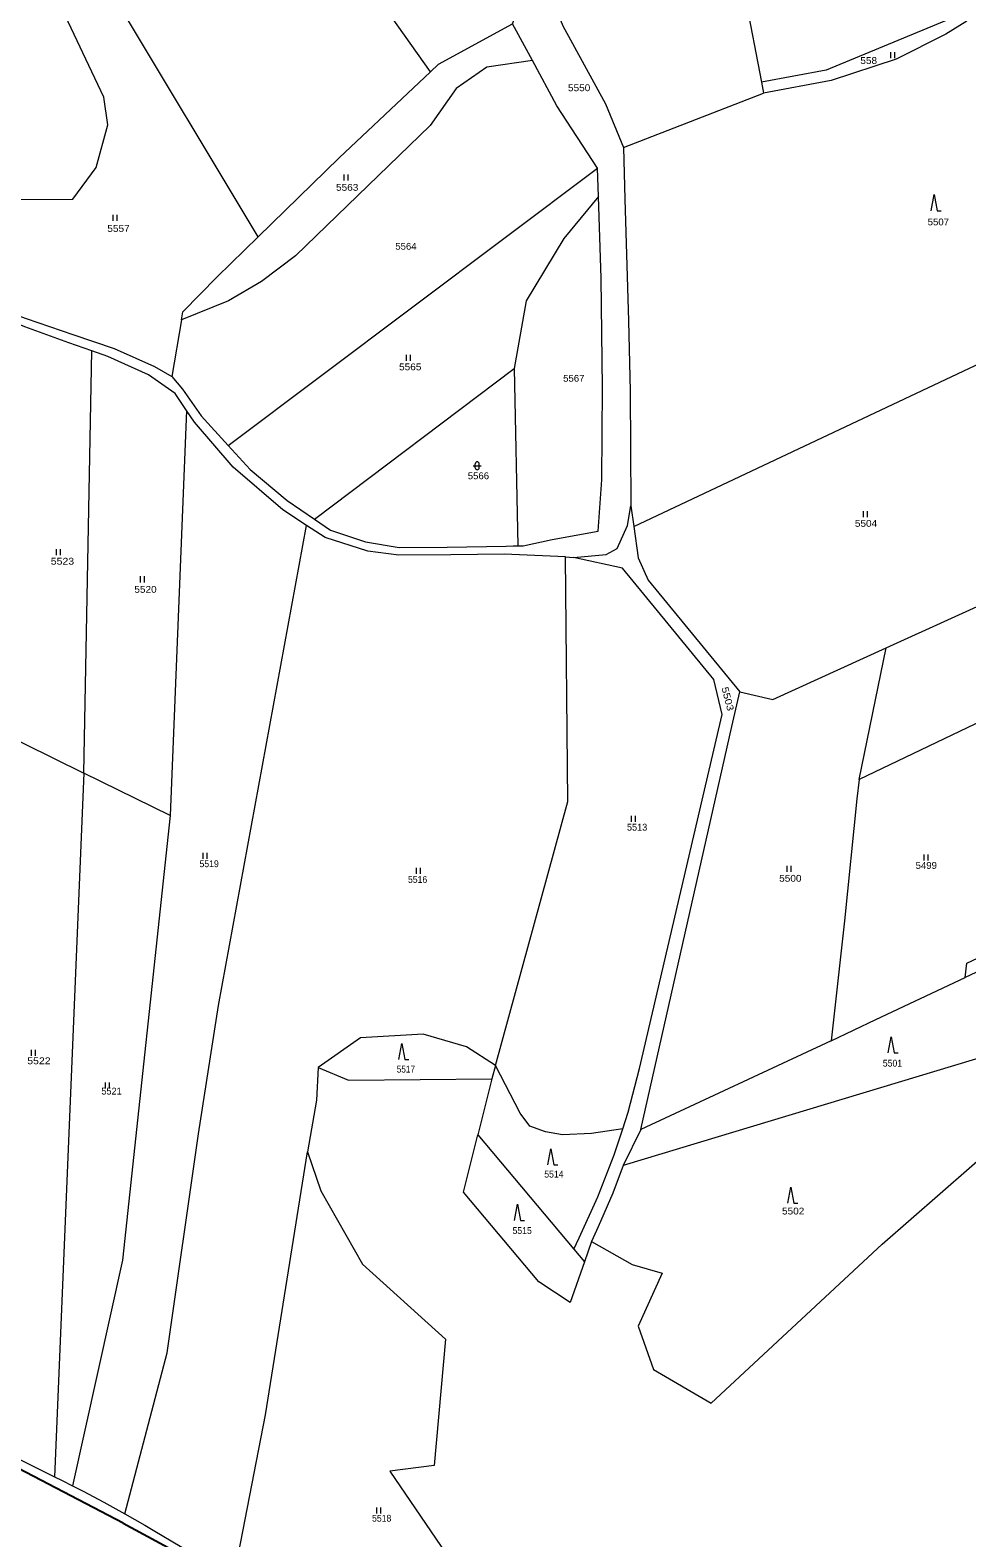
# Model space of a CAD drawing. Extents: x -590528 to -586543, y -1119609 to -1116685.
# Drawn here: x -589555 to -589321.5, y -1118965.6 to -1118589.8 of the extents above; entities that cross this region are included whole.
import ezdxf
from ezdxf.enums import TextEntityAlignment as Align

# ---------------------------------------------------------------- set-up
doc = ezdxf.new("R2010")
doc.units = 0
doc.header["$LTSCALE"] = 0.68
for name, color, linetype, lineweight in [('1', 7, 'Continuous', 13), ('3', 7, 'Continuous', 13), ('4', 7, 'Continuous', 25), ('6', 7, 'Continuous', 13)]:
    doc.layers.add(name, color=color, linetype=linetype, lineweight=lineweight)

msp = doc.modelspace()

# ---------------------------------------------------------------- linework, layer by layer
at = {"layer": '1'}
for p, q in [((-589377.91, -1118575.64), (-589372.7, -1118602.82)), ((-589498.15, -1118641.31), (-589534.97, -1118579.92)), ((-589324.31, -1118586.45), (-589356.56, -1118599.76)), ((-589429.8, -1118597.4), (-589434.75, -1118588.2)), ((-589356.56, -1118599.76), (-589372.7, -1118602.82)), ((-589372.7, -1118602.82), (-589372.18, -1118605.52)), ((-589505.53, -1118657.26), (-589517.23, -1118661.98)), ((-589484.08, -1118711.72), (-589434.36, -1118674.15)), ((-589515.97, -1118684.58), (-589520.04, -1118785.53)), ((-589405.24, -1118708.4), (-589404.53, -1118713.52)), ((-589508.04, -1118832.9), (-589486.09, -1118713.25)), ((-589420.96, -1118782.08), (-589421.59, -1118721.13)), ((-589382.53, -1118760.42), (-589384.56, -1118751.68)), ((-589380.13, -1118763.35), (-589378.14, -1118754.78)), ((-589402.77, -1118863.84), (-589380.13, -1118763.35)), ((-589541.55, -1118775), (-589548.89, -1118950.37)), ((-589520.04, -1118785.53), (-589541.55, -1118775)), ((-589348.37, -1118776.57), (-589348.94, -1118781.39)), ((-589439, -1118847.87), (-589420.96, -1118782.08)), ((-589520.04, -1118785.53), (-589531.99, -1118896.42)), ((-589513.04, -1118864.93), (-589508.04, -1118832.9)), ((-589355.38, -1118841.69), (-589402.77, -1118863.84)), ((-589446.98, -1118879.42), (-589443.41, -1118865.17)), ((-589443.41, -1118865.17), (-589419.5, -1118893.66)), ((-589402.77, -1118863.84), (-589407.16, -1118872.82)), ((-589407.16, -1118872.82), (-589409.8, -1118879.72)), ((-589419.5, -1118893.66), (-589416.85, -1118896.83)), ((-589385.25, -1118932.01), (-589342.68, -1118892.44)), ((-589557.38, -1118946.17), (-589548.89, -1118950.37)), ((-589523.89, -1118963.95), (-589504.19, -1118975.57))]:
    msp.add_line(p, q, dxfattribs=at)
for points in [[(-589455.19, -1118600.2), (-589477.85, -1118568.1), (-589490.34, -1118532.23), (-589503.08, -1118514.55)], [(-589536.6, -1118606.53), (-589558.87, -1118559.4), (-589570.68, -1118533.18), (-589560.7, -1118524.73), (-589551.05, -1118519.91), (-589569.71, -1118522), (-589581.21, -1118530.01)], [(-589455.19, -1118600.2), (-589453.19, -1118598.32), (-589434.75, -1118588.2), (-589427.97, -1118570.44), (-589423.37, -1118562.13), (-589416.01, -1118553.98), (-589405.46, -1118542.79), (-589395.65, -1118531.99), (-589381.98, -1118517.45)], [(-589383.31, -1118553.86), (-589389.82, -1118531.63), (-589409.4, -1118552.26), (-589421.86, -1118565.56), (-589425.96, -1118574.55), (-589424.61, -1118582.96), (-589422.21, -1118588.7), (-589411.59, -1118608.16)], [(-589321.57, -1118587.58), (-589326.81, -1118590.78), (-589339.12, -1118597.03), (-589355.39, -1118602.34), (-589372.18, -1118605.52)], [(-589423.74, -1118608.66), (-589429.8, -1118597.4), (-589441.19, -1118599), (-589448.81, -1118604.39)], [(-589508.4, -1118651.29), (-589498.15, -1118641.31), (-589477.95, -1118621.64), (-589455.19, -1118600.2)], [(-589448.81, -1118604.39), (-589455.26, -1118613.61), (-589488.87, -1118646.06), (-589497.28, -1118652.48), (-589505.53, -1118657.26)], [(-589411.59, -1118608.16), (-589407.1, -1118619.03), (-589372.18, -1118605.52)], [(-589568.44, -1118632.03), (-589544.29, -1118631.95), (-589538.54, -1118624.06), (-589535.64, -1118613.45), (-589536.6, -1118606.53)], [(-589505.61, -1118693.38), (-589413.55, -1118624.2), (-589423.74, -1118608.66)], [(-589407.1, -1118619.03), (-589406.77, -1118631.91), (-589405.9, -1118662.26), (-589405.43, -1118679.83), (-589405.24, -1118708.4)], [(-589412.5, -1118701.91), (-589412.33, -1118678.99), (-589412.71, -1118651.67), (-589413.33, -1118631.27), (-589413.55, -1118624.2)], [(-589413.33, -1118631.27), (-589421.95, -1118641.76), (-589431.34, -1118657.32), (-589434.36, -1118674.15)], [(-589517.23, -1118661.98), (-589516.9, -1118660.06), (-589508.4, -1118651.29)], [(-589404.53, -1118713.52), (-589319.45, -1118673.42), (-589271.29, -1118650.72), (-589254.18, -1118703.14)], [(-589565.14, -1118658.15), (-589557.12, -1118661.25), (-589555.95, -1118661.7), (-589544.29, -1118665.7), (-589534.06, -1118669.18), (-589524.02, -1118673.65), (-589519.64, -1118676.13)], [(-589539.62, -1118669.73), (-589545.34, -1118667.74), (-589556.31, -1118663.73), (-589558.69, -1118662.75)], [(-589517.23, -1118661.98), (-589519.64, -1118676.13), (-589516.98, -1118679.31), (-589512.38, -1118685.93), (-589505.61, -1118693.38)], [(-589567.43, -1118762.33), (-589564.04, -1118763.99), (-589541.55, -1118775), (-589539.62, -1118669.73)], [(-589515.97, -1118684.58), (-589518.79, -1118680.35), (-589525.5, -1118675.71), (-589535.63, -1118671.12), (-589539.62, -1118669.73)], [(-589434.36, -1118674.15), (-589433.44, -1118718.37), (-589432.1, -1118718.35), (-589424.9, -1118716.79), (-589413.39, -1118714.68), (-589412.5, -1118701.91)], [(-589504.39, -1118698.7), (-589514, -1118687.54), (-589515.97, -1118684.58)], [(-589505.61, -1118693.38), (-589500.18, -1118699.36), (-589490.93, -1118707.06), (-589484.08, -1118711.72), (-589480.12, -1118714.42), (-589471.38, -1118717.37), (-589462.99, -1118718.77), (-589451.03, -1118718.72)], [(-589486.09, -1118713.25), (-589491.99, -1118709.38), (-589504.39, -1118698.7)], [(-589256.7, -1118732.69), (-589313.85, -1118760.05), (-589348.37, -1118776.57), (-589341.68, -1118743.8), (-589294.6, -1118722.4), (-589254.18, -1118703.14)], [(-589421.59, -1118721.13), (-589419.55, -1118721.23), (-589411.44, -1118720.54), (-589408.69, -1118719.02), (-589406.14, -1118713.27), (-589405.24, -1118708.4)], [(-589450.15, -1118720.61), (-589463.09, -1118720.67), (-589470.79, -1118719.7), (-589481.48, -1118716.27), (-589486.09, -1118713.25)], [(-589404.53, -1118713.52), (-589403.45, -1118721.3), (-589400.98, -1118726.9), (-589378.14, -1118754.78)], [(-589451.03, -1118718.72), (-589436.38, -1118718.41), (-589434.64, -1118718.39), (-589433.44, -1118718.37)], [(-589421.59, -1118721.13), (-589436.83, -1118720.39), (-589450.15, -1118720.61)], [(-589384.56, -1118751.68), (-589407.33, -1118723.89), (-589419.55, -1118721.23)], [(-589378.14, -1118754.78), (-589369.9, -1118756.62), (-589341.68, -1118743.8)], [(-589407.31, -1118863.69), (-589405.95, -1118859.51), (-589403.1, -1118848.66), (-589382.53, -1118760.42)], [(-589348.94, -1118781.39), (-589352.05, -1118811.84), (-589355.38, -1118841.69), (-589344.19, -1118836.41), (-589321.93, -1118825.91)], [(-589308.68, -1118819.69), (-589321.93, -1118825.91), (-589321.52, -1118822.4), (-589295.55, -1118810.14), (-589278.56, -1118809.42), (-589264.1, -1118802.62)], [(-589439, -1118847.87), (-589446.2, -1118843.22), (-589457.04, -1118840.09), (-589472.63, -1118841.02), (-589483.18, -1118848.39)], [(-589342.68, -1118892.44), (-589306.51, -1118860.81), (-589304.51, -1118856.92), (-589306.14, -1118842.33), (-589407.16, -1118872.82)], [(-589483.18, -1118848.39), (-589483.58, -1118856.49), (-589485.85, -1118869.38), (-589482.5, -1118879.11)], [(-589483.18, -1118848.39), (-589475.67, -1118851.55), (-589439.9, -1118851.16)], [(-589413.48, -1118880.64), (-589409.42, -1118870.18), (-589407.31, -1118863.69), (-589415.12, -1118864.81), (-589422.32, -1118865.14), (-589426.54, -1118864.38), (-589430.46, -1118862.98), (-589432.85, -1118859.74), (-589439, -1118847.87), (-589439.9, -1118851.16), (-589443.41, -1118865.17)], [(-589531.99, -1118896.42), (-589544.4, -1118952.65), (-589541.79, -1118953.99), (-589536.62, -1118956.74), (-589531.38, -1118959.63), (-589520.84, -1118919.51), (-589513.04, -1118864.93)], [(-589504.19, -1118975.57), (-589496.34, -1118934.92), (-589485.85, -1118869.38)], [(-589482.5, -1118879.11), (-589472.13, -1118897.43), (-589451.47, -1118916.1), (-589454.26, -1118947.58), (-589465.34, -1118949.01), (-589450.02, -1118971.42)], [(-589415.1, -1118891.78), (-589416.85, -1118896.83), (-589420.37, -1118906.99), (-589428.21, -1118901.79), (-589446.98, -1118879.42)], [(-589419.5, -1118893.66), (-589418.13, -1118890.86), (-589413.48, -1118880.64)], [(-589409.8, -1118879.72), (-589413.43, -1118888.08), (-589415.1, -1118891.78), (-589404.91, -1118897.46), (-589397.44, -1118899.64), (-589403.43, -1118912.82), (-589399.63, -1118923.62), (-589385.25, -1118932.01)], [(-589548.89, -1118950.37), (-589547, -1118951.31), (-589544.4, -1118952.65)], [(-589531.38, -1118959.63), (-589526.41, -1118962.47), (-589523.89, -1118963.95)]]:
    msp.add_lwpolyline(points, dxfattribs=at)
at = {"layer": '4'}
for q in [(-589564.78, -1118944.76), (-589515.51, -1118970.74)]:
    msp.add_line((-589531.82, -1118961.95), q, dxfattribs=at)
at = {"layer": '6'}
for p, q in [((-589340.52, -1118596.78), (-589340.52, -1118595.28)), ((-589339.52, -1118596.78), (-589339.52, -1118595.28)), ((-589476.75, -1118627.32), (-589476.75, -1118625.82)), ((-589475.75, -1118627.32), (-589475.75, -1118625.82)), ((-589534.32, -1118637.36), (-589534.32, -1118635.86)), ((-589533.32, -1118637.36), (-589533.32, -1118635.86)), ((-589461.15, -1118672.26), (-589461.15, -1118670.76)), ((-589460.15, -1118672.26), (-589460.15, -1118670.76)), ((-589444.56, -1118698.4), (-589442.56, -1118698.4)), ((-589444.06, -1118698.9), (-589444.06, -1118697.9)), ((-589443.06, -1118698.9), (-589443.06, -1118697.9)), ((-589347.27, -1118711.23), (-589347.27, -1118709.73)), ((-589346.27, -1118711.23), (-589346.27, -1118709.73)), ((-589548.42, -1118720.64), (-589548.42, -1118719.14)), ((-589547.42, -1118720.64), (-589547.42, -1118719.14)), ((-589527.5, -1118727.45), (-589527.5, -1118725.95)), ((-589526.5, -1118727.45), (-589526.5, -1118725.95)), ((-589405.15, -1118787.16), (-589405.15, -1118785.66)), ((-589404.15, -1118787.16), (-589404.15, -1118785.66)), ((-589511.84, -1118796.4), (-589511.84, -1118794.9)), ((-589510.84, -1118796.4), (-589510.84, -1118794.9)), ((-589332.17, -1118796.79), (-589332.17, -1118795.29)), ((-589331.17, -1118796.79), (-589331.17, -1118795.29)), ((-589458.69, -1118800.12), (-589458.69, -1118798.62)), ((-589457.69, -1118800.12), (-589457.69, -1118798.62)), ((-589366.31, -1118799.62), (-589366.31, -1118798.12)), ((-589365.31, -1118799.62), (-589365.31, -1118798.12)), ((-589554.6, -1118845.5), (-589554.6, -1118844)), ((-589553.6, -1118845.5), (-589553.6, -1118844)), ((-589536.22, -1118853.62), (-589536.22, -1118852.12)), ((-589535.22, -1118853.62), (-589535.22, -1118852.12)), ((-589468.55, -1118959.52), (-589468.55, -1118958.02)), ((-589467.55, -1118959.52), (-589467.55, -1118958.02))]:
    msp.add_line(p, q, dxfattribs=at)
for points in [[(-589330.46, -1118634.82), (-589329.71, -1118630.82), (-589328.96, -1118634.82), (-589327.96, -1118634.82)], [(-589463.13, -1118846.36), (-589462.38, -1118842.36), (-589461.63, -1118846.36), (-589460.63, -1118846.36)], [(-589341.17, -1118844.72), (-589340.42, -1118840.72), (-589339.67, -1118844.72), (-589338.67, -1118844.72)], [(-589425.98, -1118872.61), (-589425.23, -1118868.61), (-589424.48, -1118872.61), (-589423.48, -1118872.61)], [(-589366.13, -1118882.22), (-589365.38, -1118878.22), (-589364.63, -1118882.22), (-589363.63, -1118882.22)], [(-589434.3, -1118886.48), (-589433.55, -1118882.48), (-589432.8, -1118886.48), (-589431.8, -1118886.48)]]:
    msp.add_lwpolyline(points, dxfattribs=at)
for centre, start, end in [((-589443.56, -1118697.9), 0, 179.99999), ((-589443.56, -1118698.9), 179.99999, 359.99999)]:
    msp.add_arc(centre, 0.5, start, end, dxfattribs=at)

# ---------------------------------------------------------------- texts
at = {"layer": '3', "width": 1.1}
msp.add_text('558', height=1.7, dxfattribs=at).set_placement((-589346, -1118598.24), align=Align.CENTER)
at = {"layer": '3'}
for s, width, p in [('5550', 1.1, (-589420.943, -1118605.03)), ('5563', 1.1, (-589478.743, -1118629.85)), ('5557', 1.1, (-589535.733, -1118640.1)), ('5507', 1.05, (-589331.303, -1118638.47)), ('5564', 1.05, (-589463.973, -1118644.54)), ('5565', 1.1, (-589463.033, -1118674.59)), ('5567', 1.05, (-589422.143, -1118677.44)), ('5566', 1.05, (-589445.913, -1118701.74)), ('5504', 1.1, (-589349.453, -1118713.6)), ('5523', 1.15, (-589549.823, -1118723.04)), ('5520', 1.1, (-589529.003, -1118730.05)), ('5519', 0.95, (-589512.763, -1118798.44)), ('5499', 1.05, (-589334.313, -1118798.86)), ('5516', 0.95, (-589460.813, -1118802.36)), ('5500', 1.1, (-589368.313, -1118802.07)), ('5522', 1.15, (-589555.693, -1118847.56)), ('5501', 0.95, (-589342.483, -1118848.15)), ('5517', 0.9, (-589463.613, -1118849.64)), ('5514', 0.95, (-589426.853, -1118875.81)), ('5502', 1.1, (-589367.603, -1118885.01)), ('5515', 0.95, (-589434.763, -1118889.86)), ('5518', 0.95, (-589469.763, -1118961.58))]:
    msp.add_text(s, height=1.7, dxfattribs=dict(at, width=width)).set_placement(p)
at = {"layer": '3', "width": 1.2}
msp.add_text('5503', height=1.7, rotation=284.474, dxfattribs=at).set_placement((-589382.701, -1118753.76))
at = {"layer": '3'}
for s, p in [('5513', (-589406.243, -1118789.33)), ('5521', (-589537.213, -1118855.11))]:
    msp.add_text(s, height=1.7, dxfattribs=at).set_placement(p)

doc.saveas('drawing.dxf')
